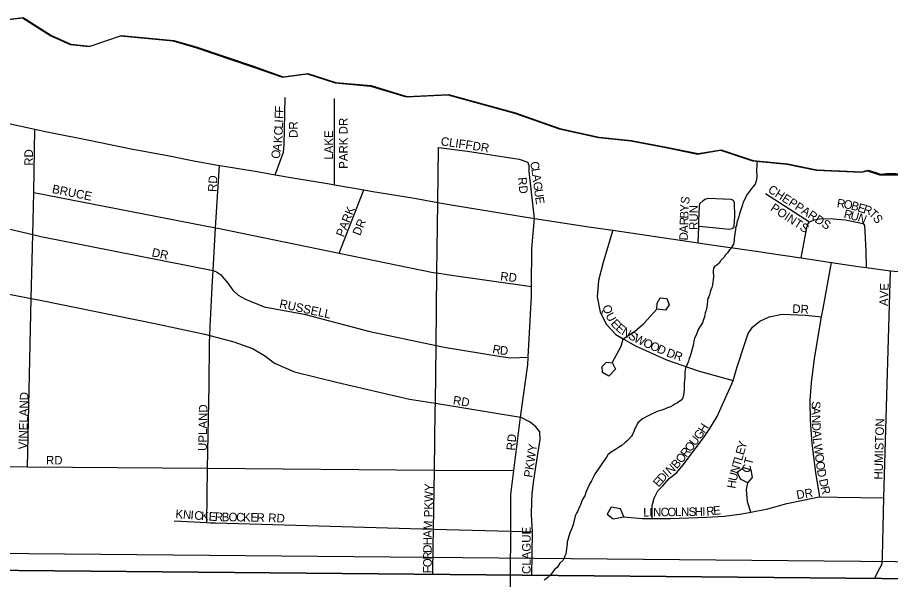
# Model space of a CAD drawing. Extents: x 2010165 to 2382125, y 1060529 to 1407316.
# Drawn here: x 2134959 to 2140046, y 1267141 to 1270442 of the extents above; entities that cross this region are included whole.
import ezdxf

# ---------------------------------------------------------------- set-up
doc = ezdxf.new("R2010")
doc.units = 0
for name, color, linetype in [('GM_X_City_Street', 7, 'Continuous'), ('GM_X_City_Street_Text', 7, 'Continuous'), ('GM_X_Corporation', 7, 'Continuous'), ('GM_X_County', 7, 'Continuous'), ('GM_X_Major_Lake', 7, 'Continuous'), ('GM_X_Major_River', 7, 'Continuous'), ('GM_X_Minor_River', 7, 'Continuous'), ('GM_X_Rail_Line', 7, 'Continuous'), ('GM_X_US_Route', 7, 'Continuous')]:
    doc.layers.add(name, color=color, linetype=linetype)

msp = doc.modelspace()

# ---------------------------------------------------------------- linework, layer by layer
at = {"layer": 'GM_X_City_Street'}
for points in [[(2136461, 1269525.1), (2136495.1, 1269618.7), (2136508.8, 1269657), (2136512.4, 1269699.1), (2136519.6, 1269976.1)], [(2136807.2, 1269466.8), (2136806.4, 1269969)], [(2135017.5, 1267822.4), (2135039.7, 1268803.2), (2135048.2, 1269175.7), (2135053.7, 1269421.2), (2135060.1, 1269790.4)], [(2137394.1, 1268190.4), (2137394.2, 1268191.9), (2137398.3, 1268529.3), (2137403.5, 1268952.1), (2137408.6, 1269363.3), (2137412.6, 1269684.4)], [(2137412.6, 1269684.4), (2137581.2, 1269662), (2137882.3, 1269615), (2137933.6, 1269598.2)], [(2137971.6, 1269269.2), (2137939.8, 1269544.1), (2137939.7, 1269578.2), (2137933.6, 1269598.2)], [(2136061.5, 1267497.1), (2136066.9, 1267813.9), (2136075.2, 1268298.1), (2136078.7, 1268542.9), (2136080.2, 1268587.9), (2136081.8, 1268637.3), (2136093.5, 1268872.1), (2136098.6, 1268965.8), (2136113.8, 1269216), (2136136, 1269579.4)], [(2136833.3, 1269068.4), (2136977.1, 1269437.1)], [(2134045.6, 1269398.7), (2134365, 1269335.8), (2134459.4, 1269316.8), (2134521.6, 1269303.3), (2134646.3, 1269270.5), (2135048.2, 1269175.7), (2135094.4, 1269164.8), (2136098.6, 1268965.8)], [(2135053.7, 1269421.2), (2136113.8, 1269216), (2136136.3, 1269211.7), (2136833.3, 1269068.4), (2137381.7, 1268955.7), (2137403.5, 1268952.1), (2137474, 1268940.6), (2137955.1, 1268873.3)], [(2138926, 1269127.9), (2138928.4, 1269223.9), (2138929, 1269256), (2138933.2, 1269342), (2138935.9, 1269357), (2138952.3, 1269372.1), (2138964.6, 1269381.6), (2138985, 1269387.7), (2139114.8, 1269382.9), (2139128.4, 1269376.1), (2139135.2, 1269362.5), (2139137.9, 1269283.9), (2139133.8, 1269221.8), (2139122.9, 1269209.5), (2139105.1, 1269205.5), (2139030, 1269213.7), (2138930.4, 1269223.9)], [(2139318.2, 1269414.9), (2139574.8, 1269251.1)], [(2137831.8, 1267121.4), (2137832.1, 1267187.5), (2137833, 1267446), (2137833.7, 1267660.1), (2137850.8, 1267799.3), (2137889.3, 1268111), (2137933.1, 1268415.6), (2137935.5, 1268460.6), (2137954.8, 1268816.5), (2137955.1, 1268873.3), (2137956.6, 1269095), (2137971.6, 1269269.2)], [(2139525.1, 1269039.9), (2139554.3, 1269196.5), (2139562.6, 1269233.4), (2139574.8, 1269251.1), (2139603.5, 1269262), (2139643.8, 1269270), (2139711.4, 1269267.4), (2139782.4, 1269261.9), (2139886.1, 1269240), (2139894.3, 1269229.2), (2139902.5, 1269081.7), (2139903.2, 1268983.4)], [(2138427.2, 1269201.1), (2138373.3, 1269020.1), (2138344.4, 1268907.4), (2138337.3, 1268813), (2138354.2, 1268723), (2138391, 1268651.1), (2138445.7, 1268593.5), (2138487.8, 1268568.9), (2138560.7, 1268526.4), (2138739.8, 1268446), (2138924.9, 1268381.7), (2139128.4, 1268325.4)], [(2139633.9, 1267646.5), (2139610.4, 1267788.8), (2139588.6, 1267957.2), (2139579.3, 1268091.5), (2139578.1, 1268209.9), (2139585.1, 1268312.3), (2139603.8, 1268452.9), (2139644.8, 1268695.6), (2139653, 1268744.4), (2139701.4, 1269013.2)], [(2136098.6, 1268965.8), (2136119.2, 1268959.3), (2136142.5, 1268943.6), (2136184.3, 1268893.3), (2136214.2, 1268851.1), (2136244.1, 1268822.9), (2136288, 1268798.6), (2136395.9, 1268754.1), (2136629.9, 1268711), (2137011.9, 1268611.2), (2137398.3, 1268529.3), (2137445.9, 1268519.2), (2137778, 1268465.7), (2137832, 1268457.4), (2137935.5, 1268460.6)], [(2139953.4, 1267170.7), (2139984.7, 1267230.9), (2139996.5, 1267255.1), (2140000.1, 1267299.3), (2140006.7, 1267640.4), (2140045.4, 1268964.7)], [(2134829.5, 1268843.2), (2135039.7, 1268803.2), (2135091.6, 1268793.4), (2135760, 1268657.8), (2136050.2, 1268596), (2136080.2, 1268587.9), (2136220.3, 1268550.1), (2136328.3, 1268512.1), (2136398.4, 1268470.1), (2136456.5, 1268426.1), (2136572.6, 1268376.1), (2136826.7, 1268314.3), (2137243, 1268216.5), (2137394.2, 1268191.9), (2137889.3, 1268111)], [(2138425.3, 1268426.7), (2138443.7, 1268390.8), (2138404, 1268350.3), (2138367.7, 1268371.9), (2138365.4, 1268406), (2138391.2, 1268432.4), (2138423.3, 1268428.7), (2138476.5, 1268525.5), (2138487.8, 1268568.9), (2138553.8, 1268610.7), (2138607.5, 1268655.3), (2138684.8, 1268740.4), (2138686.5, 1268776.5), (2138704.2, 1268806.8), (2138742.3, 1268803.2), (2138756.7, 1268767.2), (2138735, 1268734.9), (2138686.8, 1268740.4)], [(2138656.8, 1267520.2), (2138658.1, 1267596.4), (2138669.6, 1267638.7), (2138689.3, 1267681), (2138719, 1267711.4), (2138756.7, 1267753.9), (2138800.5, 1267788.5), (2138838.1, 1267833), (2138956.8, 1267990.8), (2138992.4, 1268045.3), (2139035.8, 1268116), (2139075, 1268202.7), (2139122.1, 1268305.5), (2139128.4, 1268325.4), (2139153.2, 1268404.1), (2139199.9, 1268547.1), (2139217.4, 1268599.4), (2139241.2, 1268635.8), (2139284.9, 1268670.4), (2139338.8, 1268697), (2139414.8, 1268711.8), (2139553.2, 1268705.2), (2139644.8, 1268695.6)], [(2137382, 1267360.4), (2137383.5, 1267458.6), (2137388.5, 1267803.1), (2137393.7, 1268151.2), (2137394.1, 1268190.4)], [(2137955.8, 1267189.1), (2137959.5, 1267442.4), (2137955, 1267541), (2137956.2, 1267619.2), (2137957.8, 1267663.4), (2137965.1, 1267729.7), (2137980.2, 1267822.2), (2137996.1, 1267932.5), (2138004.7, 1267980.9), (2138002.3, 1268025.1), (2137979.9, 1268054.9), (2137945.6, 1268082.7), (2137889.3, 1268111)], [(2133972.9, 1267830.9), (2135017.5, 1267822.4), (2136066.9, 1267813.9), (2137388.5, 1267803.1), (2137850.8, 1267799.3)], [(2139232.5, 1267557.9), (2139213.1, 1267618.2), (2139206.4, 1267690.4), (2139214, 1267728.6), (2139241.8, 1267758.9), (2139233.3, 1267805), (2139189.1, 1267816.6), (2139153.3, 1267788.1), (2139169.7, 1267752.2), (2139212, 1267730.6)], [(2138492.3, 1267530.5), (2138471.8, 1267576.4), (2138417.6, 1267585.9), (2138395.9, 1267545.5), (2138430.3, 1267517.8), (2138492.3, 1267530.5), (2138598.7, 1267519.5), (2138656.8, 1267520.2), (2138765, 1267521.3), (2138973.4, 1267527.4), (2139079.6, 1267534.6), (2139179.7, 1267547.6), (2139232.5, 1267557.9), (2139331.8, 1267577.3), (2139441.7, 1267608.5), (2139537.7, 1267627.6), (2139629.8, 1267646.6), (2139633.9, 1267646.5), (2139736.2, 1267644.9)], [(2139736.2, 1267644.9), (2139737.5, 1267644.8), (2140006.7, 1267640.4)], [(2135871.5, 1267507.6), (2136061.5, 1267497.1)], [(2136061.5, 1267497.1), (2136082.3, 1267495.9), (2136113.9, 1267494.2), (2137383.5, 1267458.6), (2137833, 1267446), (2137959.5, 1267442.4)], [(2137379.6, 1267194.4), (2137382, 1267360.4), (2137382, 1267360.4)]]:
    msp.add_lwpolyline(points, dxfattribs=at)
at = {"layer": 'GM_X_Corporation'}
for points in [[(2134805.2, 1270418.4), (2134987.7, 1270439.4), (2135152.7, 1270333.8), (2135265.3, 1270284.2), (2135377.8, 1270272.7), (2135560.1, 1270333.8), (2135865.3, 1270305.1), (2135995.9, 1270267.6), (2136323.5, 1270156.8), (2136502.4, 1270093.5), (2136646.8, 1270112.2), (2136809.5, 1270060.9), (2137016.3, 1270041.8), (2137223.3, 1269978.6), (2137466.1, 1269989.8), (2137855.9, 1269883.3), (2138115.2, 1269792.2), (2138344.2, 1269741.2), (2138532.9, 1269722), (2138745.8, 1269680.9), (2138920.5, 1269645.6), (2139054.9, 1269668.3), (2139241.8, 1269605), (2139442.6, 1269585.9), (2139613.3, 1269550.6), (2139876.2, 1269539.8), (2139911.5, 1269548.5), (2139982.3, 1269525), (2140248.3, 1269523.4)], [(2113929.8, 1250070.4), (2113971.4, 1267404), (2121968.1, 1267337), (2140205.4, 1267168.3), (2140069, 1257837), (2140063.6, 1257468.8), (2140046.9, 1256760.6)], [(2140205.4, 1267168.3), (2121968.1, 1267337)]]:
    msp.add_lwpolyline(points, dxfattribs=at)
at = {"layer": 'GM_X_County'}
msp.add_lwpolyline([(2134805.2, 1270418.4), (2134987.7, 1270439.4), (2135152.7, 1270333.8), (2135265.3, 1270284.2), (2135377.8, 1270272.7), (2135560.1, 1270333.8), (2135865.3, 1270305.1), (2135995.9, 1270267.6), (2136323.5, 1270156.8), (2136502.4, 1270093.5), (2136646.8, 1270112.2), (2136809.5, 1270060.9), (2137016.3, 1270041.8), (2137223.3, 1269978.6), (2137466.1, 1269989.8), (2137855.9, 1269883.3), (2138115.2, 1269792.2), (2138344.2, 1269741.2), (2138532.9, 1269722), (2138745.8, 1269680.9), (2138920.5, 1269645.6), (2139054.9, 1269668.3), (2139241.8, 1269605), (2139442.6, 1269585.9), (2139613.3, 1269550.6), (2139876.2, 1269539.8), (2139911.5, 1269548.5), (2139956.2, 1269534.8), (2139982.3, 1269525), (2140038.4, 1269531.3), (2140144.7, 1269526)], dxfattribs=at)
at = {"layer": 'GM_X_Major_Lake'}
for points in [[(2134809.4, 1270421), (2134992, 1270441.9), (2135157, 1270336.4), (2135269.6, 1270286.7), (2135382, 1270275.2)], [(2134809.4, 1270421), (2134992, 1270441.9), (2135157, 1270336.4), (2135269.6, 1270286.7), (2135382, 1270275.2)], [(2135382, 1270275.2), (2135564.4, 1270336.3), (2135869.5, 1270307.7), (2136000.1, 1270270.2), (2136327.7, 1270159.4), (2136506.6, 1270096), (2136651, 1270114.8), (2136813.8, 1270063.4), (2137020.6, 1270044.3), (2137227.6, 1269981.1), (2137470.3, 1269992.3), (2137860.1, 1269885.8), (2138119.4, 1269794.8), (2138348.4, 1269743.7), (2138537.1, 1269724.6), (2138750.1, 1269683.4), (2138924.8, 1269648.1), (2139059.1, 1269670.9), (2139246.1, 1269607.6), (2139446.8, 1269588.4), (2139617.6, 1269553.2), (2139880.5, 1269542.4)], [(2139880.5, 1269542.4), (2139915.8, 1269551), (2139960.5, 1269537.4), (2139986.6, 1269527.5), (2140042.7, 1269533.9), (2140149, 1269528.5)], [(2139880.5, 1269542.4), (2139915.8, 1269551), (2139960.5, 1269537.4), (2139986.6, 1269527.5), (2140042.7, 1269533.9), (2140149, 1269528.5)]]:
    msp.add_lwpolyline(points, dxfattribs=at)
at = {"layer": 'GM_X_Major_River'}
for points in [[(2134809.4, 1270421), (2134992, 1270441.9), (2135157, 1270336.4), (2135269.6, 1270286.7), (2135382, 1270275.2)], [(2135382, 1270275.2), (2135564.4, 1270336.3), (2135869.5, 1270307.7), (2136000.1, 1270270.2), (2136327.7, 1270159.4), (2136506.6, 1270096), (2136651, 1270114.8), (2136813.8, 1270063.4), (2137020.6, 1270044.3), (2137227.6, 1269981.1), (2137470.3, 1269992.3), (2137860.1, 1269885.8), (2138119.4, 1269794.8), (2138348.4, 1269743.7), (2138537.1, 1269724.6), (2138750.1, 1269683.4), (2138924.8, 1269648.1), (2139059.1, 1269670.9), (2139246.1, 1269607.6), (2139446.8, 1269588.4), (2139617.6, 1269553.2), (2139880.5, 1269542.4)]]:
    msp.add_lwpolyline(points, dxfattribs=at)
at = {"layer": 'GM_X_Minor_River'}
for points in [[(2139268.1, 1269605.5), (2139264.9, 1269552.5), (2139264.9, 1269538.4), (2139267, 1269526.4), (2139267, 1269514.3), (2139265.1, 1269500.3), (2139263.1, 1269488.2), (2139257.1, 1269470.2), (2139245.1, 1269456.1), (2139235.2, 1269444), (2139223.2, 1269425.9), (2139213.2, 1269413.8), (2139205.2, 1269399.8), (2139197.2, 1269381.7), (2139187.3, 1269365.6), (2139183.3, 1269349.5), (2139177.3, 1269331.4), (2139171.4, 1269313.4), (2139163.4, 1269289.3), (2139159.5, 1269273.2), (2139153.5, 1269257.1), (2139151.5, 1269247.1), (2139149.6, 1269237.1), (2139147.6, 1269225), (2139143.6, 1269213), (2139143.7, 1269202.9), (2139141.7, 1269192.9), (2139135.8, 1269152.7), (2139135.9, 1269140.7), (2139131.9, 1269120.6), (2139119.9, 1269100.5), (2139108, 1269086.4), (2139096, 1269070.3), (2139084, 1269058.3), (2139076, 1269044.2), (2139066, 1269032.1), (2139056, 1269022.1), (2139048, 1269010), (2139034, 1268997.9), (2139022, 1268991.8), (2139014, 1268979.8), (2139012.1, 1268961.7), (2139012.1, 1268951.7), (2139014.1, 1268941.7), (2139014.2, 1268929.6), (2139012.2, 1268911.6), (2139010.3, 1268899.5), (2139008.3, 1268883.4), (2139004.4, 1268867.4), (2138998.4, 1268853.3), (2138994.4, 1268839.3), (2138990.5, 1268825.2), (2138986.5, 1268813.2), (2138982.5, 1268803.1), (2138980.5, 1268793.1), (2138980.6, 1268783), (2138978.6, 1268773), (2138976.6, 1268754.9), (2138972.7, 1268734.9), (2138966.7, 1268718.8), (2138962.8, 1268696.7), (2138954.8, 1268674.6), (2138950.9, 1268660.6), (2138942.9, 1268650.5), (2138930.9, 1268632.4), (2138924.9, 1268622.3), (2138920.9, 1268610.3), (2138913, 1268590.2), (2138903, 1268572.1), (2138899.1, 1268556), (2138897.1, 1268536), (2138893.2, 1268515.9), (2138879.3, 1268467.7), (2138873.3, 1268453.6), (2138869.4, 1268437.6), (2138859.4, 1268415.4), (2138851.4, 1268397.4), (2138847.5, 1268373.3), (2138847.6, 1268357.2), (2138847.6, 1268341.2), (2138845.7, 1268325.1), (2138843.7, 1268309.1), (2138843.8, 1268293), (2138843.8, 1268274.9), (2138841.9, 1268254.9), (2138839.9, 1268240.8), (2138836, 1268224.8), (2138832, 1268214.7), (2138818, 1268204.6), (2138804, 1268194.6), (2138790, 1268186.5), (2138777.9, 1268178.4), (2138763.9, 1268172.3), (2138745.9, 1268166.3), (2138719.8, 1268154.1), (2138685.8, 1268144), (2138657.7, 1268129.9), (2138629.7, 1268117.8), (2138601.6, 1268101.6), (2138585.6, 1268087.5), (2138573.6, 1268077.4)], [(2138573.6, 1268077.4), (2138567.6, 1268065.4), (2138559.6, 1268051.3), (2138553.7, 1268041.3), (2138549.7, 1268027.2), (2138541.7, 1268011.1), (2138537.7, 1268001.1), (2138521.8, 1267983), (2138511.8, 1267972.9), (2138497.8, 1267960.8), (2138479.7, 1267946.7), (2138461.7, 1267934.6), (2138443.7, 1267922.5), (2138423.7, 1267910.4), (2138409.7, 1267902.3), (2138399.7, 1267892.3), (2138391.7, 1267878.2), (2138363.7, 1267840), (2138355.7, 1267827.9), (2138347.7, 1267815.9), (2138337.8, 1267801.8), (2138325.8, 1267783.7), (2138315.8, 1267763.6), (2138303.9, 1267739.5), (2138291.9, 1267721.4), (2138281.9, 1267699.3), (2138272, 1267677.2), (2138264, 1267653.1), (2138254.1, 1267635), (2138246.1, 1267616.9), (2138240.1, 1267600.8), (2138234.1, 1267588.8), (2138228.2, 1267574.7), (2138222.2, 1267560.6), (2138216.2, 1267550.6), (2138208.2, 1267536.5), (2138204.3, 1267516.4), (2138200.3, 1267502.4), (2138196.4, 1267484.3), (2138186.4, 1267458.2), (2138178.5, 1267440.1), (2138172.5, 1267418), (2138166.6, 1267395.9), (2138162.6, 1267383.9), (2138162.6, 1267373.8), (2138160.7, 1267357.8), (2138158.7, 1267341.7), (2138156.8, 1267329.7), (2138154.8, 1267313.6), (2138148.8, 1267303.6), (2138144.9, 1267291.5), (2138136.9, 1267275.4), (2138118.9, 1267259.3), (2138112.9, 1267249.3), (2138102.9, 1267235.2), (2138088.9, 1267223.1), (2138068.9, 1267195), (2138050.9, 1267178.8), (2138038.9, 1267168.8), (2138028.9, 1267160.7), (2138028.9, 1267160.7)]]:
    msp.add_lwpolyline(points, dxfattribs=at)
at = {"layer": 'GM_X_Rail_Line'}
msp.add_lwpolyline([(2113972.9, 1267502.1), (2117240.2, 1267485.7), (2117936.8, 1267482.1), (2118637, 1267476.4), (2119207.2, 1267469.2), (2120788.3, 1267454.9), (2122004.3, 1267442.8), (2123412.6, 1267429.2), (2125388.1, 1267409.2), (2126127.6, 1267400.6), (2127231.4, 1267389.9), (2130406.6, 1267359.9), (2132736.5, 1267337.1), (2134810.6, 1267317.8), (2139871.2, 1267271.3), (2143552.9, 1267237)], dxfattribs=at)
at = {"layer": 'GM_X_US_Route'}
for points in [[(2134732.5, 1269861.4), (2134970.9, 1269809.2), (2135060.1, 1269790.4), (2135133.1, 1269775.1), (2135377.5, 1269726.9), (2135621.9, 1269676.8), (2135834.2, 1269636.6), (2135996.5, 1269604.5), (2136136, 1269579.4), (2136152.7, 1269576.4), (2136367.1, 1269542.3), (2136461, 1269525.1), (2136575.4, 1269504.1), (2136777.7, 1269472), (2136807.2, 1269466.8), (2136977.1, 1269437.1), (2137030.1, 1269427.8), (2137260.5, 1269389.7), (2137408.6, 1269363.3), (2137474.9, 1269351.5), (2137699.2, 1269313.4), (2137971.6, 1269269.2), (2138288.1, 1269221), (2138427.2, 1269201.1), (2138624.7, 1269172.8), (2138926, 1269127.9), (2138961.2, 1269122.6), (2139264.1, 1269078.7), (2139279.7, 1269076.4), (2139325.5, 1269069.6)], [(2139325.5, 1269069.6), (2139525.1, 1269039.9), (2139536.2, 1269038.3), (2139701.4, 1269013.2), (2139857.3, 1268989.5), (2139903.2, 1268983.4), (2140045.4, 1268964.7), (2140177.7, 1268952.5), (2140193.4, 1268952), (2140317.4, 1268948.3)]]:
    msp.add_lwpolyline(points, dxfattribs=at)

# ---------------------------------------------------------------- texts
at = {"layer": 'GM_X_City_Street_Text'}
for s, rotation, p in [('F', 87.8688, (2136507.2, 1269849.9)), ('F', 87.889, (2136508.5, 1269885.1)), ('I', 87.8881, (2136506.4, 1269828)), ('PARK DR', 90, (2136882.5, 1269559.5)), ('C', 87.891, (2136503.7, 1269753.2)), ('L', 87.8824, (2136505.1, 1269792.8)), ('DR', 90, (2136591.2, 1269739.9)), ('K', 86.874, (2136501.2, 1269708.3)), ('LAKE', 90, (2136797.1, 1269612.3)), ('CLIFF', 352.3021, (2137423.2, 1269696.4)), ('A', 80.2464, (2136493, 1269658.7)), ('DR', 351.0318, (2137608.2, 1269670)), ('RD', 90, (2135049.7, 1269577.1)), ('O', 78.8487, (2136484.3, 1269614.2)), ('C', 280.4764, (2137945.7, 1269597.8)), ('L', 278.0162, (2137952.8, 1269559.4)), ('RD', 86.9884, (2136118.9, 1269423.6)), ('RD', 276.0111, (2137874.6, 1269507.6)), ('A', 277.6618, (2137957.7, 1269524.6)), ('G', 277.6674, (2137963.6, 1269481)), ('BRUCE', 348.6915, (2135157.8, 1269419.1)), ('U', 277.6618, (2137969.4, 1269437.4)), ('CHEPPARDS', 327.3082, (2139327.8, 1269426.6)), ('E', 277.662, (2137975.3, 1269393.8)), ('S', 79.7966, (2138870.3, 1269350.2)), ('R', 351.6415, (2139731.2, 1269335.8)), ('O', 351.6426, (2139770.3, 1269330)), ('PARK', 68.1986, (2136859.4, 1269158)), ('Y', 88.3433, (2138869.3, 1269308.2)), ('RUN', 90, (2138923.2, 1269203.1)), ('POINTS', 326.6335, (2139342.2, 1269319.5)), ('B', 343.7544, (2139812.1, 1269324)), ('E', 342.144, (2139849.8, 1269313.1)), ('R', 342.1461, (2139883.3, 1269302.3)), ('T', 316.3812, (2139915.9, 1269293.1)), ('B', 88.3428, (2138868.1, 1269268.6)), ('R', 346.8179, (2139770.5, 1269274.3)), ('U', 346.4091, (2139809, 1269265.3)), ('N', 338.4705, (2139850, 1269255.5)), ('S', 306.5748, (2139939.9, 1269270.5)), ('DR', 67.6224, (2136955.1, 1269165.5)), ('A', 88.3433, (2138865.7, 1269185.1)), ('R', 88.3484, (2138867, 1269229.1)), ('D', 88.3494, (2138864.5, 1269141.1)), ('DR', 348.1073, (2135738.6, 1269049.5)), ('RD', 353.9946, (2137770.5, 1268908.9)), ('AVE', 88.0261, (2140030.5, 1268759)), ('RUSSELL', 347.7737, (2136482.1, 1268750.4)), ('DR', 356.8219, (2139472.8, 1268719.7)), ('Q', 284.6618, (2138367.4, 1268759.1)), ('U', 298.6013, (2138383.4, 1268704.2)), ('E', 312.7969, (2138412.3, 1268654.6)), ('E', 318.6101, (2138440.2, 1268624.9)), ('N', 329.2728, (2138474.8, 1268595.7)), ('S', 330.2484, (2138513.5, 1268572.7)), ('W', 333.3423, (2138546.6, 1268553.9)), ('O', 336.2006, (2138600.2, 1268527)), ('R', 348.2852, (2137723.5, 1268486.2)), ('D', 354.9047, (2137768.4, 1268477.3)), ('O', 336.3856, (2138640.6, 1268509.2)), ('D', 336.3637, (2138680.9, 1268491.6)), ('D', 339.4923, (2138736.2, 1268467.8)), ('R', 341.4254, (2138779.2, 1268451.8)), ('VINELAND', 88.4098, (2135014.5, 1267922.9)), ('RD', 350.5308, (2137493.9, 1268187.2)), ('UPLAND', 88.9775, (2136061.7, 1267914.1)), ('S', 270.0547, (2139587.3, 1268204.3)), ('A', 270.0437, (2139587.3, 1268169.1)), ('N', 271.1196, (2139587.4, 1268124.1)), ('H', 56.8919, (2138962.6, 1268013.9)), ('D', 273.546, (2139588.4, 1268077.8)), ('HUMISTON', 88.4315, (2139999.7, 1267747)), ('RD', 83.9946, (2137856.9, 1267914.9)), ('U', 52.3914, (2138907.7, 1267939.7)), ('G', 54.5279, (2138935.8, 1267976.2)), ('A', 273.8742, (2139591.1, 1268033.6)), ('PKWY', 81.4687, (2137958.2, 1267756.9)), ('O', 52.3932, (2138880.9, 1267904.9)), ('Y', 74.0649, (2139199.9, 1267921.3)), ('L', 274.8693, (2139594.1, 1267988.7)), ('W', 277.2085, (2139597.4, 1267951.4)), ('R', 52.3534, (2138856.7, 1267873.5)), ('E', 74.0519, (2139190.2, 1267887.5)), ('RD', 0, (2135125.1, 1267835.3)), ('B', 48.1115, (2138800.2, 1267806.5)), ('O', 51.4261, (2138828.7, 1267838.4)), ('T', 74.0519, (2139170.9, 1267819.8)), ('L', 74.0519, (2139180.6, 1267853.6)), ('CT', 74.4796, (2139225.4, 1267782.5)), ('O', 277.5526, (2139604.6, 1267894.4)), ('O', 277.7025, (2139610.4, 1267850.6)), ('I', 41.6444, (2138746.1, 1267758.3)), ('N', 41.2579, (2138762.5, 1267772.9)), ('N', 74.0606, (2139158.8, 1267777.5)), ('D', 281.006, (2139616.8, 1267803.9)), ('E', 48.7601, (2138695, 1267699.9)), ('D', 48.7808, (2138718.3, 1267726.4)), ('U', 76.3295, (2139148.6, 1267735.2)), ('D', 282.7276, (2139628.4, 1267746.2)), ('PKWY', 88.6009, (2137377.3, 1267526.9)), ('H', 80.6131, (2139141.6, 1267692.8)), ('R', 282.7224, (2139638.1, 1267703.3)), ('DR', 8.9682, (2139501.6, 1267632.8)), ('K', 355.7781, (2135878.2, 1267522.9)), ('N', 355.7815, (2135922.1, 1267519.6)), ('I', 355.79, (2135966, 1267516.4)), ('C', 355.7708, (2135987.9, 1267514.8)), ('K', 355.7815, (2136027.4, 1267511.9)), ('E', 356.0959, (2136071.6, 1267508.6)), ('R', 358.1643, (2136108.7, 1267506.1)), ('B', 359.0441, (2136149.1, 1267504.8)), ('O', 359.1145, (2136188.8, 1267504.1)), ('C', 359.1014, (2136232.8, 1267503.5)), ('K', 359.1145, (2136272.4, 1267502.8)), ('E', 359.0984, (2136316.4, 1267502.2)), ('R', 359.1152, (2136351.6, 1267501.6)), ('RD', 356.9887, (2136419.2, 1267500.9)), ('L', 0.7104, (2138605.4, 1267531.7)), ('I', 0.6995, (2138640.6, 1267532.1)), ('N', 0.6995, (2138662.6, 1267532.4)), ('C', 0.68, (2138706.6, 1267532.9)), ('O', 0.6966, (2138746.2, 1267533.4)), ('L', 0.6983, (2138790.2, 1267534)), ('N', 0.6995, (2138825.4, 1267534.4)), ('S', 0.683, (2138869.4, 1267534.9)), ('H', 0.6966, (2138904.6, 1267535.3)), ('I', 1.9692, (2138949.8, 1267535.9)), ('R', 5.0004, (2138974.7, 1267536.9)), ('E', 6.0021, (2139015.1, 1267540.4)), ('M', 85.7885, (2137373.3, 1267450.9)), ('A', 89.6284, (2137373, 1267407.8)), ('CLAGUE', 90, (2137949.3, 1267196.7)), ('H', 89.9645, (2137373, 1267363.9)), ('D', 89.9672, (2137373, 1267319.9)), ('R', 89.9703, (2137372.9, 1267280.3)), ('O', 89.9645, (2137372.9, 1267236.3)), ('F', 89.9727, (2137372.9, 1267201.1))]:
    msp.add_text(s, height=50, rotation=rotation, dxfattribs=at).set_placement(p)

doc.saveas('drawing.dxf')
